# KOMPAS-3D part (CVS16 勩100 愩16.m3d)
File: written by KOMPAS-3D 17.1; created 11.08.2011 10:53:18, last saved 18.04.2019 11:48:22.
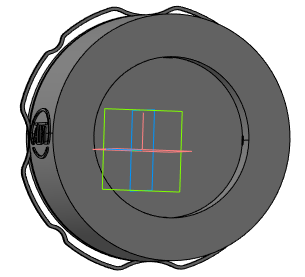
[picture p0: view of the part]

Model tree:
1. Плоскость XY
2. Плоскость ZX
3. Плоскость ZY
4. Ось X
5. Ось Y
6. Ось Z
7. Начало координат
8. Операция без истории:2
